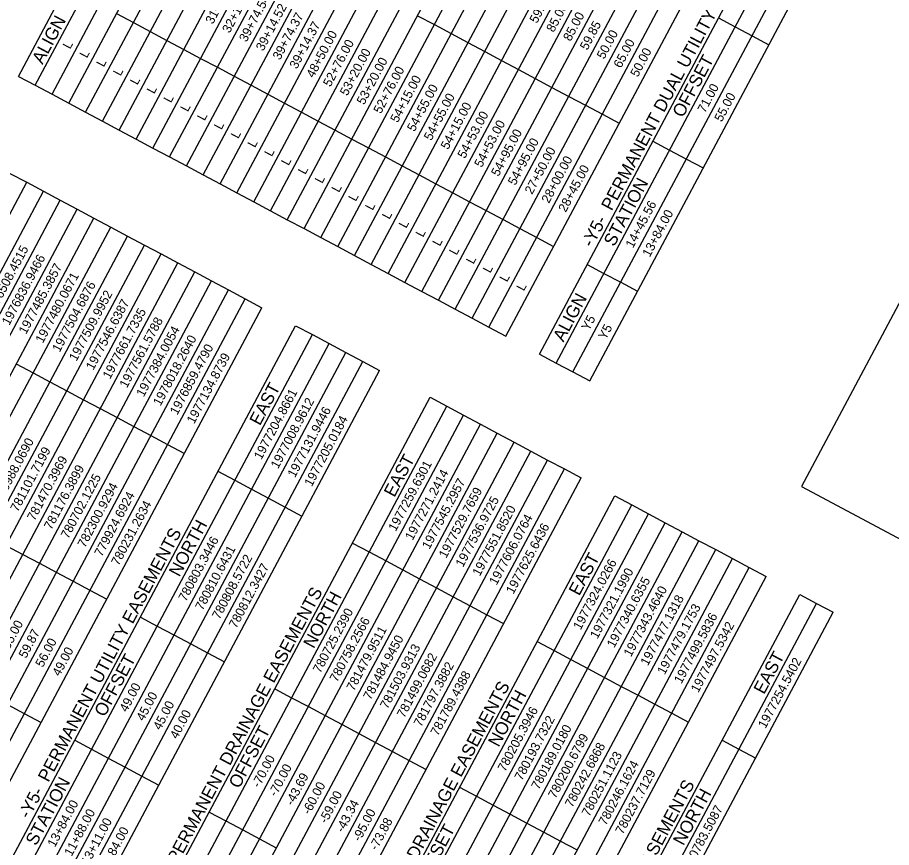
# Model space of a CAD drawing. Extents: x 1979034 to 1987549, y 771535 to 781988.
# Drawn here: x 1983234 to 1985403, y 777368 to 779426 of the extents above; entities that cross this region are included whole.
import ezdxf

# ---------------------------------------------------------------- set-up
doc = ezdxf.new("R2010")
doc.units = 0
for name, color, linetype in [('CTL Sheet Notes CELL', 7, 'Continuous'), ('CTL Sheet Table Cell', 7, 'Continuous'), ('CTL Sheet Text', 7, 'Continuous'), ('Old_Level_2', 7, 'Continuous')]:
    doc.layers.add(name, color=color, linetype=linetype)

msp = doc.modelspace()

# ---------------------------------------------------------------- linework, layer by layer
at = {"layer": 'CTL Sheet Table Cell'}
for p, q in [((1983236.6, 779280.3), (1984066.2, 780837)), ((1983278.3, 779258.1), (1984107.9, 780814.8)), ((1983320, 779235.9), (1984149.6, 780792.6)), ((1983361.7, 779213.6), (1984191.3, 780770.4)), ((1983403.4, 779191.4), (1984233, 780748.2)), ((1983445.1, 779169.2), (1984274.7, 780725.9)), ((1983486.8, 779147), (1984316.4, 780703.7)), ((1983528.5, 779124.7), (1984358.1, 780681.5)), ((1983570.2, 779102.5), (1984399.8, 780659.3)), ((1983611.9, 779080.3), (1984441.5, 780637.1)), ((1983653.6, 779058.1), (1984483.2, 780614.8)), ((1983695.3, 779035.9), (1984524.9, 780592.6)), ((1983737, 779013.6), (1984566.6, 780570.4)), ((1983778.7, 778991.4), (1984608.3, 780548.2)), ((1983820.4, 778969.2), (1984650, 780526)), ((1983862.1, 778947), (1984691.7, 780503.7)), ((1983903.8, 778924.8), (1984733.4, 780481.5)), ((1983945.5, 778902.5), (1984775.1, 780459.3)), ((1983987.2, 778880.3), (1984816.8, 780437.1)), ((1984028.9, 778858.1), (1984858.5, 780414.8)), ((1984070.6, 778835.9), (1984900.2, 780392.6)), ((1984112.3, 778813.7), (1984941.9, 780370.4)), ((1984154, 778791.4), (1984983.6, 780348.2)), ((1984195.7, 778769.2), (1985025.3, 780326)), ((1984237.4, 778747), (1985067, 780303.7)), ((1984279.1, 778724.8), (1985108.7, 780281.5)), ((1984320.8, 778702.5), (1985150.4, 780259.3)), ((1984362.5, 778680.3), (1985192.1, 780237.1)), ((1984404.2, 778658.1), (1985233.8, 780214.9)), ((1984445.9, 778635.9), (1985275.5, 780192.6)), ((1984529.3, 778591.4), (1985358.9, 780148.2)), ((1984571, 778569.2), (1985400.6, 780126)), ((1984612.7, 778547), (1985442.3, 780103.8)), ((1984654.4, 778524.8), (1985484, 780081.5)), ((1983480.2, 779436), (1983521.9, 779413.8)), ((1983521.9, 779413.8), (1983563.6, 779391.6)), ((1984227, 779430.7), (1984268.7, 779408.5)), ((1984973.7, 779425.4), (1985015.4, 779403.2)), ((1983563.6, 779391.6), (1983605.3, 779369.4)), ((1984268.7, 779408.5), (1984310.4, 779386.3)), ((1985015.4, 779403.2), (1985057.1, 779381)), ((1983605.3, 779369.4), (1983647, 779347.1)), ((1984310.4, 779386.3), (1984352.1, 779364.1)), ((1985057.1, 779381), (1985098.8, 779358.8)), ((1983647, 779347.1), (1983688.7, 779324.9)), ((1984352.1, 779364.1), (1984393.8, 779341.8)), ((1983688.7, 779324.9), (1983730.4, 779302.7)), ((1984393.8, 779341.8), (1984435.5, 779319.6)), ((1984435.5, 779319.6), (1984477.2, 779297.4)), ((1983730.4, 779302.7), (1983772.1, 779280.5)), ((1984477.2, 779297.4), (1984518.9, 779275.2)), ((1983236.6, 779280.3), (1983278.3, 779258.1)), ((1983772.1, 779280.5), (1983813.8, 779258.3)), ((1984518.9, 779275.2), (1984560.6, 779253)), ((1983278.3, 779258.1), (1983320, 779235.9)), ((1983813.8, 779258.3), (1983855.5, 779236)), ((1984560.6, 779253), (1984602.3, 779230.7)), ((1983320, 779235.9), (1983361.7, 779213.6)), ((1983855.5, 779236), (1983897.2, 779213.8)), ((1984602.3, 779230.7), (1984644, 779208.5)), ((1983361.7, 779213.6), (1983403.4, 779191.4)), ((1983897.2, 779213.8), (1983938.9, 779191.6)), ((1984644, 779208.5), (1984685.7, 779186.3)), ((1983403.4, 779191.4), (1983445.1, 779169.2)), ((1983938.9, 779191.6), (1983980.6, 779169.4)), ((1984685.7, 779186.3), (1984727.4, 779164.1)), ((1983445.1, 779169.2), (1983486.8, 779147)), ((1983980.6, 779169.4), (1984022.3, 779147.2)), ((1983486.8, 779147), (1983528.5, 779124.7)), ((1984022.3, 779147.2), (1984064, 779124.9)), ((1983528.5, 779124.7), (1983570.2, 779102.5)), ((1984064, 779124.9), (1984105.7, 779102.7)), ((1984810.8, 779119.6), (1984852.5, 779097.4)), ((1983570.2, 779102.5), (1983611.9, 779080.3)), ((1984105.7, 779102.7), (1984147.4, 779080.5)), ((1984852.5, 779097.4), (1984894.2, 779075.2)), ((1983611.9, 779080.3), (1983653.6, 779058.1)), ((1984147.4, 779080.5), (1984189.1, 779058.3)), ((1984894.2, 779075.2), (1984935.9, 779053)), ((1983653.6, 779058.1), (1983695.3, 779035.9)), ((1984189.1, 779058.3), (1984230.8, 779036)), ((1983215.5, 779039.7), (1983257.2, 779017.5)), ((1983695.3, 779035.9), (1983737, 779013.6)), ((1984230.8, 779036), (1984272.5, 779013.8)), ((1982427.6, 777460.7), (1983257.2, 779017.5)), ((1983257.2, 779017.5), (1983298.9, 778995.3)), ((1983737, 779013.6), (1983778.7, 778991.4)), ((1984272.5, 779013.8), (1984314.2, 778991.6)), ((1982469.3, 777438.5), (1983298.9, 778995.3)), ((1983298.9, 778995.3), (1983340.6, 778973)), ((1983778.7, 778991.4), (1983820.4, 778969.2)), ((1984314.2, 778991.6), (1984355.9, 778969.4)), ((1982511, 777416.3), (1983340.6, 778973)), ((1983340.6, 778973), (1983382.3, 778950.8)), ((1983820.4, 778969.2), (1983862.1, 778947)), ((1984355.9, 778969.4), (1984397.6, 778947.2)), ((1982552.7, 777394.1), (1983382.3, 778950.8)), ((1983382.3, 778950.8), (1983424, 778928.6)), ((1983862.1, 778947), (1983903.8, 778924.8)), ((1984397.6, 778947.2), (1984439.3, 778924.9)), ((1982594.4, 777371.8), (1983424, 778928.6)), ((1983424, 778928.6), (1983465.7, 778906.4)), ((1983903.8, 778924.8), (1983945.5, 778902.5)), ((1984439.3, 778924.9), (1984481, 778902.7)), ((1982636.1, 777349.6), (1983465.7, 778906.4)), ((1983465.7, 778906.4), (1983507.4, 778884.1)), ((1983945.5, 778902.5), (1983987.2, 778880.3)), ((1984481, 778902.7), (1984522.7, 778880.5)), ((1982677.8, 777327.4), (1983507.4, 778884.1)), ((1983507.4, 778884.1), (1983549.1, 778861.9)), ((1983987.2, 778880.3), (1984028.9, 778858.1)), ((1984522.7, 778880.5), (1984564.4, 778858.3)), ((1982719.5, 777305.2), (1983549.1, 778861.9)), ((1983549.1, 778861.9), (1983590.8, 778839.7)), ((1984028.9, 778858.1), (1984070.6, 778835.9)), ((1982761.2, 777283), (1983590.8, 778839.7)), ((1983590.8, 778839.7), (1983632.5, 778817.5)), ((1984070.6, 778835.9), (1984112.3, 778813.7)), ((1982802.9, 777260.7), (1983632.5, 778817.5)), ((1983632.5, 778817.5), (1983674.2, 778795.3)), ((1984112.3, 778813.7), (1984154, 778791.4)), ((1984647.8, 778813.8), (1984689.5, 778791.6)), ((1982844.6, 777238.5), (1983674.2, 778795.3)), ((1983674.2, 778795.3), (1983715.9, 778773)), ((1984154, 778791.4), (1984195.7, 778769.2)), ((1984689.5, 778791.6), (1984731.2, 778769.4)), ((1982886.3, 777216.3), (1983715.9, 778773)), ((1983715.9, 778773), (1983757.6, 778750.8)), ((1984195.7, 778769.2), (1984237.4, 778747)), ((1984731.2, 778769.4), (1984772.9, 778747.2)), ((1982928, 777194.1), (1983757.6, 778750.8)), ((1983757.6, 778750.8), (1983799.3, 778728.6)), ((1984237.4, 778747), (1984279.1, 778724.8)), ((1982969.7, 777171.8), (1983799.3, 778728.6)), ((1983799.3, 778728.6), (1983841, 778706.4)), ((1984279.1, 778724.8), (1984320.8, 778702.5)), ((1983011.4, 777149.6), (1983841, 778706.4)), ((1984320.8, 778702.5), (1984362.5, 778680.3)), ((1984362.5, 778680.3), (1984404.2, 778658.1)), ((1983094.8, 777105.2), (1983924.4, 778661.9)), ((1983924.4, 778661.9), (1983966.1, 778639.7)), ((1984404.2, 778658.1), (1984445.9, 778635.9)), ((1983136.5, 777083), (1983966.1, 778639.7)), ((1983966.1, 778639.7), (1984007.8, 778617.5)), ((1983178.2, 777060.7), (1984007.8, 778617.5)), ((1984007.8, 778617.5), (1984049.5, 778595.3)), ((1983219.9, 777038.5), (1984049.5, 778595.3)), ((1984049.5, 778595.3), (1984091.2, 778573.1)), ((1984529.3, 778591.4), (1984571, 778569.2)), ((1983231.4, 778567.2), (1983273.1, 778545)), ((1983261.6, 777016.3), (1984091.2, 778573.1)), ((1984091.2, 778573.1), (1984132.9, 778550.8)), ((1984571, 778569.2), (1984612.7, 778547)), ((1983273.1, 778545), (1983314.8, 778522.8)), ((1983303.3, 776994.1), (1984132.9, 778550.8)), ((1984612.7, 778547), (1984654.4, 778524.8)), ((1983314.8, 778522.8), (1983356.5, 778500.5)), ((1983356.5, 778500.5), (1983398.2, 778478.3)), ((1983428.4, 776927.4), (1984258, 778484.2)), ((1984258, 778484.2), (1984299.7, 778462)), ((1983398.2, 778478.3), (1983439.9, 778456.1)), ((1983470.1, 776905.2), (1984299.7, 778462)), ((1984299.7, 778462), (1984341.4, 778439.7)), ((1983439.9, 778456.1), (1983481.6, 778433.9)), ((1983511.8, 776883), (1984341.4, 778439.7)), ((1984341.4, 778439.7), (1984383.1, 778417.5)), ((1983481.6, 778433.9), (1983523.3, 778411.7)), ((1983553.5, 776860.8), (1984383.1, 778417.5)), ((1984383.1, 778417.5), (1984424.8, 778395.3)), ((1983523.3, 778411.7), (1983565, 778389.4)), ((1983595.2, 776838.5), (1984424.8, 778395.3)), ((1984424.8, 778395.3), (1984466.5, 778373.1)), ((1983565, 778389.4), (1983606.7, 778367.2)), ((1983636.9, 776816.3), (1984466.5, 778373.1)), ((1984466.5, 778373.1), (1984508.2, 778350.8)), ((1983606.7, 778367.2), (1983648.4, 778345)), ((1983678.6, 776794.1), (1984508.2, 778350.8)), ((1984508.2, 778350.8), (1984549.9, 778328.6)), ((1983720.3, 776771.9), (1984549.9, 778328.6)), ((1984549.9, 778328.6), (1984591.6, 778306.4)), ((1983762, 776749.6), (1984591.6, 778306.4)), ((1984591.6, 778306.4), (1984633.3, 778284.2)), ((1983731.8, 778300.6), (1983773.5, 778278.3)), ((1983803.7, 776727.4), (1984633.3, 778284.2)), ((1983773.5, 778278.3), (1983815.2, 778256.1)), ((1983815.2, 778256.1), (1983856.9, 778233.9)), ((1983856.9, 778233.9), (1983898.6, 778211.7)), ((1983887.1, 776683), (1984716.7, 778239.7)), ((1984716.7, 778239.7), (1984758.4, 778217.5)), ((1983898.6, 778211.7), (1983940.3, 778189.4)), ((1983928.8, 776660.8), (1984758.4, 778217.5)), ((1984758.4, 778217.5), (1984800.1, 778195.3)), ((1983970.5, 776638.5), (1984800.1, 778195.3)), ((1984800.1, 778195.3), (1984841.7, 778173.1)), ((1984012.2, 776616.3), (1984841.7, 778173.1)), ((1984841.7, 778173.1), (1984883.4, 778150.9)), ((1984053.9, 776594.1), (1984883.4, 778150.9)), ((1984883.4, 778150.9), (1984925.1, 778128.6)), ((1983205.6, 778116.9), (1983247.3, 778094.7)), ((1984065.4, 778122.8), (1984107.1, 778100.6)), ((1984095.6, 776571.9), (1984925.1, 778128.6)), ((1984925.1, 778128.6), (1984966.8, 778106.4)), ((1983247.3, 778094.7), (1983289, 778072.5)), ((1984107.1, 778100.6), (1984148.8, 778078.3)), ((1984137.3, 776549.7), (1984966.8, 778106.4)), ((1984966.8, 778106.4), (1985008.5, 778084.2)), ((1983289, 778072.5), (1983330.7, 778050.3)), ((1984148.8, 778078.3), (1984190.5, 778056.1)), ((1984179, 776527.4), (1985008.5, 778084.2)), ((1985008.5, 778084.2), (1985050.2, 778062)), ((1983330.7, 778050.3), (1983372.4, 778028)), ((1984190.5, 778056.1), (1984232.2, 778033.9)), ((1984220.7, 776505.2), (1985050.2, 778062)), ((1985050.2, 778062), (1985091.9, 778039.8)), ((1983372.4, 778028), (1983414.1, 778005.8)), ((1984232.2, 778033.9), (1984273.9, 778011.7)), ((1984262.4, 776483), (1985091.9, 778039.8)), ((1983414.1, 778005.8), (1983455.8, 777983.6)), ((1984273.9, 778011.7), (1984315.6, 777989.5)), ((1984315.6, 777989.5), (1984357.3, 777967.2)), ((1984345.8, 776438.6), (1985175.3, 777995.3)), ((1985175.3, 777995.3), (1985217, 777973.1)), ((1984357.3, 777967.2), (1984399, 777945)), ((1984387.5, 776416.3), (1985217, 777973.1)), ((1985217, 777973.1), (1985258.7, 777950.9)), ((1983539.2, 777939.2), (1983580.9, 777916.9)), ((1984399, 777945), (1984440.7, 777922.8)), ((1984429.2, 776394.1), (1985258.7, 777950.9)), ((1983580.9, 777916.9), (1983622.6, 777894.7)), ((1983622.6, 777894.7), (1983664.3, 777872.5)), ((1983664.3, 777872.5), (1983706, 777850.3)), ((1984524.1, 777878.4), (1984565.8, 777856.1)), ((1983706, 777850.3), (1983747.7, 777828.1)), ((1984565.8, 777856.1), (1984607.5, 777833.9)), ((1984607.5, 777833.9), (1984649.2, 777811.7)), ((1984649.2, 777811.7), (1984690.9, 777789.5)), ((1984690.9, 777789.5), (1984732.6, 777767.2)), ((1984732.6, 777767.2), (1984774.3, 777745)), ((1983872.8, 777761.4), (1983914.5, 777739.2)), ((1984774.3, 777745), (1984816, 777722.8)), ((1983209.5, 777722.3), (1983251.2, 777700)), ((1983914.5, 777739.2), (1983956.2, 777717)), ((1984816, 777722.8), (1984857.7, 777700.6)), ((1983251.2, 777700), (1983292.9, 777677.8)), ((1983956.2, 777717), (1983997.9, 777694.7)), ((1984857.7, 777700.6), (1984899.4, 777678.4)), ((1983997.9, 777694.7), (1984039.6, 777672.5)), ((1984039.6, 777672.5), (1984081.3, 777650.3)), ((1983376.3, 777633.4), (1983418, 777611.1)), ((1984081.3, 777650.3), (1984123, 777628.1)), ((1984982.8, 777633.9), (1985024.5, 777611.7)), ((1983418, 777611.1), (1983459.7, 777588.9)), ((1984123, 777628.1), (1984164.7, 777605.8)), ((1985024.5, 777611.7), (1985066.2, 777589.5)), ((1984164.7, 777605.8), (1984206.4, 777583.6)), ((1983459.7, 777588.9), (1983501.4, 777566.7)), ((1984206.4, 777583.6), (1984248.1, 777561.4)), ((1983501.4, 777566.7), (1983543.1, 777544.5)), ((1983543.1, 777544.5), (1983584.8, 777522.3)), ((1984331.5, 777517), (1984373.2, 777494.7)), ((1984373.2, 777494.7), (1984414.9, 777472.5)), ((1984414.9, 777472.5), (1984456.6, 777450.3)), ((1983709.8, 777455.6), (1983751.5, 777433.4)), ((1984456.6, 777450.3), (1984498.3, 777428.1)), ((1983751.5, 777433.4), (1983793.2, 777411.2)), ((1984498.3, 777428.1), (1984540, 777405.9)), ((1983793.2, 777411.2), (1983834.9, 777388.9)), ((1984540, 777405.9), (1984581.7, 777383.6)), ((1983834.9, 777388.9), (1983876.6, 777366.7)), ((1984581.7, 777383.6), (1984623.4, 777361.4))]:
    msp.add_line(p, q, dxfattribs=at)
at = {"layer": 'Old_Level_2'}
msp.add_lwpolyline([(1986199.1, 777719.5), (1987047.7, 779311.9), (1986028.5, 779855), (1985179.9, 778262.6)], close=True, dxfattribs=at)

# ---------------------------------------------------------------- texts
at = {"layer": 'CTL Sheet Notes CELL'}
for s, p in [('-Y5-  PERMANENT DUAL UTILITY EASEMENTS', (1984660.3, 778854.1)), ('ALIGN', (1983296.3, 779308.6)), ('OFFSET', (1984885.3, 779175.9)), ('STATION', (1984715, 778856.3)), ('ALIGN', (1984589, 778619.8)), ('EAST', (1983835.9, 778412.2)), ('EAST', (1984169.5, 778234.4)), ('NORTH', (1983636, 778037)), ('-Y5-  PERMANENT UTILITY EASEMENTS', (1983262.6, 777436.8)), ('EAST', (1984628.2, 777990)), ('-L-  PERMANENT DRAINAGE EASEMENTS', (1983596.2, 777259)), ('NORTH', (1983969.5, 777859.2)), ('OFFSET', (1983450.8, 777689.6)), ('EAST', (1985086.9, 777745.5)), ('-Y4-  PERMANENT DRAINAGE EASEMENTS', (1984047.5, 777000.8)), ('NORTH', (1984428.2, 777614.8)), ('OFFSET', (1983784.4, 777511.8)), ('STATION', (1983280.5, 777370)), ('-Y5-  PERMANENT DRAINAGE EASEMENTS', (1984506.2, 776756.4)), ('NORTH', (1984886.9, 777370.4)), ('OFFSET', (1984243.1, 777267.4))]:
    msp.add_text(s, height=31.5, rotation=61.9471, dxfattribs=at).set_placement(p)
at = {"layer": 'CTL Sheet Text'}
for s, p in [('31+90.00', (1983719, 779408.1)), ('32+10.00', (1983760.7, 779385.9)), ('39+74.54', (1983802.4, 779363.7)), ('59.84', (1984523.2, 779410.1)), ('39+14.52', (1983844.1, 779341.5)), ('85.00', (1984564.9, 779387.9)), ('39+74.37', (1983885.8, 779319.2)), ('85.00', (1984606.6, 779365.7)), ('39+14.37', (1983927.5, 779297)), ('59.85', (1984648.3, 779343.5)), ('48+50.00', (1983969.2, 779274.8)), ('50.00', (1984690, 779321.3)), ('52+76.00', (1984010.9, 779252.6)), ('65.00', (1984731.7, 779299)), ('L', (1983364.9, 779346.3)), ('53+20.00', (1984052.6, 779230.3)), ('50.00', (1984773.4, 779276.8)), ('L', (1983406.6, 779324.1)), ('53+20.00', (1984094.3, 779208.1)), ('L', (1983448.3, 779301.9)), ('52+76.00', (1984136, 779185.9)), ('L', (1983490, 779279.6)), ('54+15.00', (1984177.7, 779163.7)), ('L', (1983531.7, 779257.4)), ('54+55.00', (1984219.4, 779141.5)), ('71.00', (1984940.2, 779187.9)), ('L', (1983573.4, 779235.2)), ('54+55.00', (1984261.1, 779119.2)), ('55.00', (1984981.9, 779165.7)), ('L', (1983615.1, 779213)), ('L', (1983656.8, 779190.8)), ('54+15.00', (1984302.8, 779097)), ('L', (1983698.5, 779168.5)), ('54+53.00', (1984344.5, 779074.8)), ('L', (1983740.2, 779146.3)), ('54+53.00', (1984386.2, 779052.6)), ('L', (1983781.9, 779124.1)), ('54+95.00', (1984427.9, 779030.4)), ('L', (1983823.5, 779101.9)), ('54+95.00', (1984469.6, 779008.1)), ('L', (1983865.2, 779079.7)), ('27+50.00', (1984511.3, 778985.9)), ('L', (1983906.9, 779057.4)), ('28+00.00', (1984553, 778963.7)), ('L', (1983948.6, 779035.2)), ('28+45.00', (1984594.7, 778941.5)), ('L', (1983990.3, 779013)), ('L', (1984032, 778990.8)), ('L', (1984073.7, 778968.5)), ('L', (1984115.4, 778946.3)), ('14+45.56', (1984761.5, 778852.6)), ('L', (1984157.1, 778924.1)), ('13+84.00', (1984803.2, 778830.4)), ('L', (1984198.8, 778901.9)), ('L', (1984240.5, 778879.7)), ('L', (1984282.2, 778857.4)), ('1976508.4515', (1983172.1, 778683.2)), ('L', (1984323.9, 778835.2)), ('1976836.9466', (1983213.8, 778661)), ('L', (1984365.6, 778813)), ('1977485.3857', (1983255.5, 778638.8)), ('L', (1984407.3, 778790.8)), ('1977480.0671', (1983297.2, 778616.6)), ('L', (1984449, 778768.6)), ('1977504.6876', (1983338.9, 778594.4)), ('L', (1984490.7, 778746.3)), ('1977509.9952', (1983380.6, 778572.1)), ('1977546.6387', (1983422.3, 778549.9)), ('1977661.7335', (1983464, 778527.7)), ('1977561.5788', (1983505.7, 778505.5)), ('Y5', (1984652.3, 778647.6)), ('1977384.0054', (1983547.4, 778483.3)), ('Y5', (1984694, 778625.4)), ('1978018.2640', (1983589.1, 778461)), ('1976859.4790', (1983630.8, 778438.8)), ('1977134.8739', (1983672.5, 778416.6)), ('1977204.8661', (1983839.3, 778327.7)), ('1977008.9612', (1983881, 778305.5)), ('1977131.9446', (1983922.7, 778283.3)), ('1977205.0184', (1983964.4, 778261)), ('780988.0690', (1983193.3, 778220.6)), ('781101.7199', (1983235, 778198.4)), ('781470.3969', (1983276.7, 778176.2)), ('781176.3899', (1983318.4, 778153.9)), ('1977259.6301', (1984172.9, 778149.9)), ('780702.1225', (1983360.1, 778131.7)), ('1977271.2414', (1984214.6, 778127.7)), ('1977545.2957', (1984256.3, 778105.5)), ('782300.9294', (1983401.8, 778109.5)), ('779924.6924', (1983443.5, 778087.3)), ('1977529.7659', (1984298, 778083.3)), ('780231.2634', (1983485.2, 778065)), ('1977536.9725', (1984339.7, 778061.1)), ('1977551.8520', (1984381.4, 778038.8)), ('1977606.0764', (1984423.1, 778016.6)), ('1977625.6436', (1984464.8, 777994.4)), ('780803.3446', (1983652, 777976.2)), ('780810.6431', (1983693.7, 777953.9)), ('780808.5722', (1983735.4, 777931.7)), ('780812.3427', (1983777.1, 777909.5)), ('1977324.0266', (1984631.6, 777905.5)), ('1977321.1990', (1984673.3, 777883.3)), ('1977340.6355', (1984715, 777861.1)), ('1977343.4640', (1984756.7, 777838.8)), ('1977477.1318', (1984798.4, 777816.6)), ('780725.2390', (1983985.6, 777798.4)), ('1977479.1753', (1984840.1, 777794.4)), ('780758.2566', (1984027.3, 777776.2)), ('1977499.5836', (1984881.8, 777772.2)), ('55.00', (1983213.8, 777857.2)), ('1977497.5342', (1984923.5, 777750)), ('59.87', (1983255.5, 777835)), ('781479.9511', (1984069, 777754)), ('781484.9450', (1984110.7, 777731.7)), ('56.00', (1983297.2, 777812.8)), ('781503.9313', (1984152.4, 777709.5)), ('49.00', (1983338.9, 777790.6)), ('781499.0682', (1984194.1, 777687.3)), ('1977254.5402', (1985090.3, 777661.1)), ('781797.3882', (1984235.8, 777665.1)), ('781789.4388', (1984277.5, 777642.8)), ('49.00', (1983505.7, 777701.7)), ('45.00', (1983547.4, 777679.5)), ('45.00', (1983589.1, 777657.2)), ('40.00', (1983630.8, 777635)), ('780205.3946', (1984444.3, 777554)), ('780193.7322', (1984486, 777531.7)), ('780189.0180', (1984527.7, 777509.5)), ('780200.6799', (1984569.4, 777487.3)), ('780242.6868', (1984611.1, 777465.1)), ('-70.00', (1983834.1, 777514.1)), ('780251.1123', (1984652.8, 777442.9)), ('-70.00', (1983875.8, 777491.8)), ('780246.1624', (1984694.5, 777420.6)), ('-43.69', (1983917.5, 777469.6)), ('780237.7129', (1984736.2, 777398.4)), ('-60.00', (1983959.2, 777447.4)), ('-59.00', (1984000.9, 777425.2)), ('13+84.00', (1983327, 777366.3)), ('-43.34', (1984042.6, 777403)), ('11+88.00', (1983368.7, 777344.1)), ('-95.00', (1984084.2, 777380.7)), ('780783.5087', (1984903, 777309.5)), ('13+11.00', (1983410.4, 777321.9)), ('-73.88', (1984125.9, 777358.5)), ('13+84.00', (1983452.1, 777299.7))]:
    msp.add_text(s, height=22.5, rotation=61.9471, dxfattribs=at).set_placement(p)

doc.saveas('drawing.dxf')
